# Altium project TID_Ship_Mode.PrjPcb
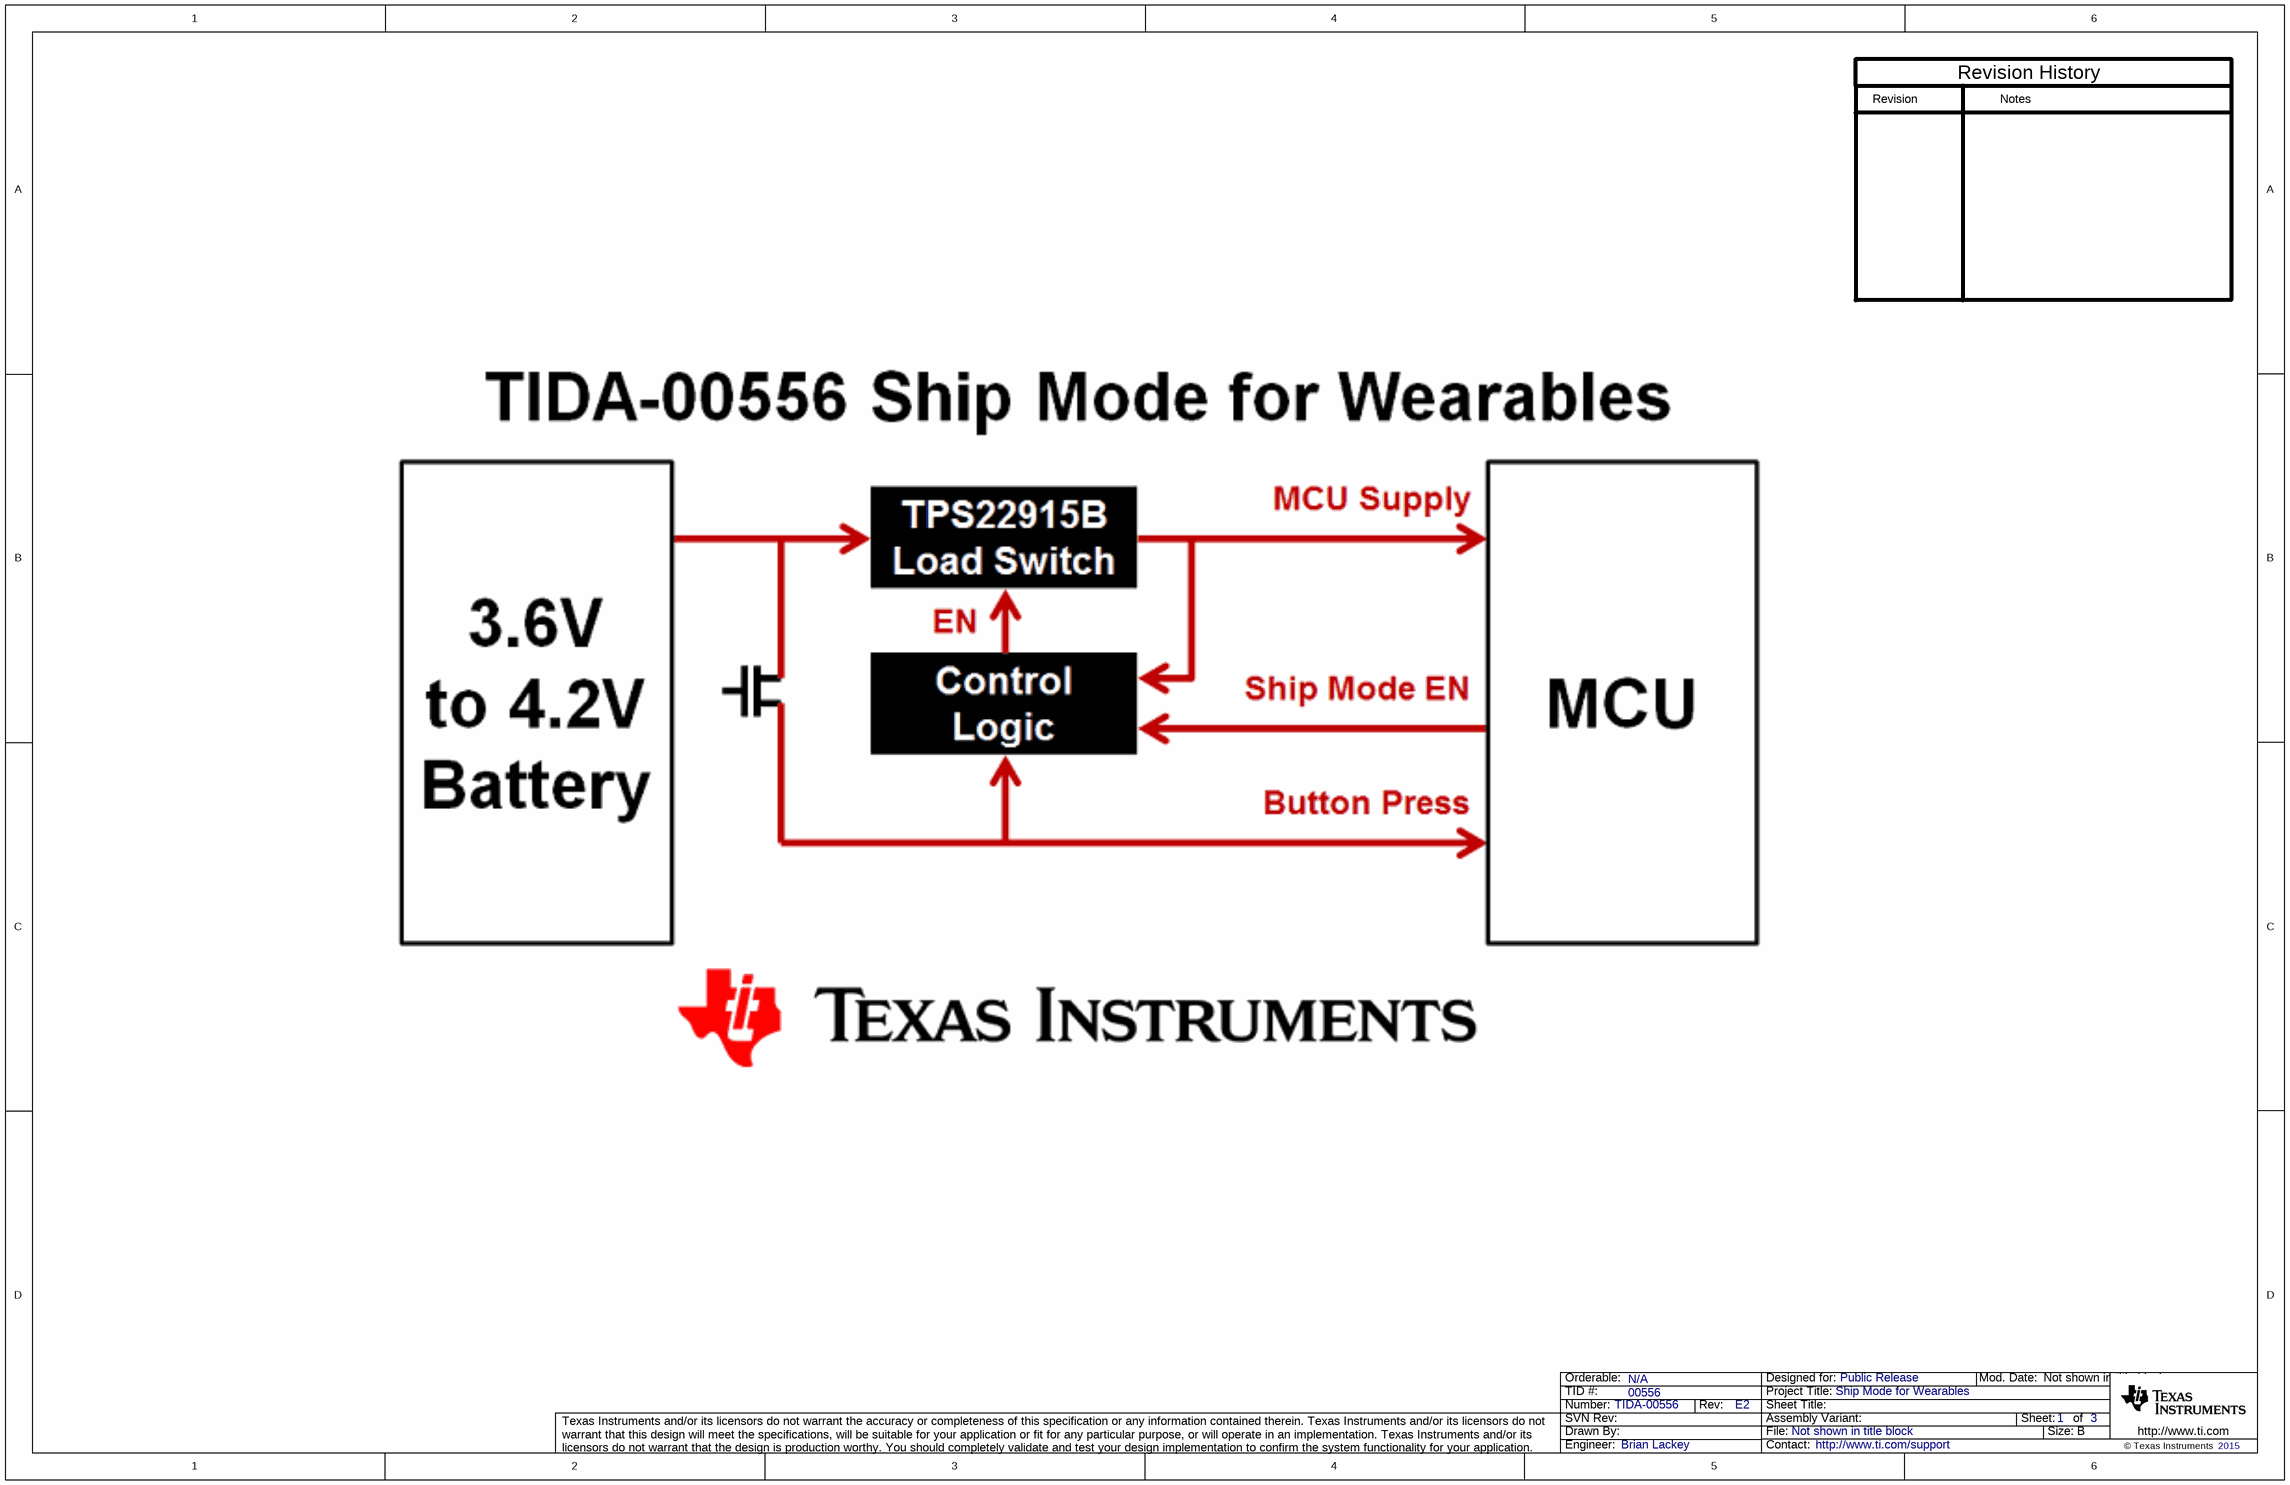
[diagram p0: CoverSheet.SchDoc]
CopyrightYear: 2015; EVM_Orderable: N/A; PCB_Rev: E2; PRJ_Customer: Public Release; PRJ_Engineer: Brian Lackey; PRJ_Number: TIDA-00556; PRJ_Title: Ship Mode for Wearables; SCH_Rev: E2; TechSupport: http://www.ti.com/support; TID: 00556
3 sheets, 41 parts. Net scope: global (net labels, ports and power ports of the same name join across sheets).
Board file: TID.PcbDoc
Sheets:
  CoverSheet.SchDoc
  TID_Hardware.SchDoc
  Ship_Mode_Circuit.SchDoc

## Sheet CoverSheet.SchDoc
size 431 x 279 mm; Date: Not shown in title block; ApprovedBy: Not shown in title block; CheckedBy: Not shown in title block; Author: Not shown in title block; CompanyName: Not shown in title block; Engineer: Not shown in title block; Organization: Not shown in title block; Address1: Not shown in title block; Address2: Not shown in title block; Address3: Not shown in title block; Address4: Not shown in title block; DocumentNumber: 1; Revision: Use project parameter SCH_Rev; SheetNumber: 1; SheetTotal: 3; PageSetup: Record=PageOptions¦CenterHorizontal=True¦CenterVertical=True¦PrintScale=1.00¦XCorrection=1.00¦YCorrection=1.00¦PrintKind=0¦BorderSize=5000000¦LeftOffset=0¦BottomOffset=0¦Orientation=2¦PaperLength=1000¦PaperWidth=1000¦Scale=100¦PaperSource=15¦PrintQuality=600¦MediaType=1¦DitherType=10¦PaperKind=Letter¦PrintScaleMode=1

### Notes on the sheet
- Revision
- Notes
- Revision History
- Place Block Diagram here (if appropriate) or delete this text box.
  If using a block diagram from another tool, save the picture as a .bmp file.
  Then, use menu Place|Drawing Tools|Graphic to insert the .png/.svg/.bmp file on the schematic.

## Sheet TID_Hardware.SchDoc
size 431 x 279 mm; Date: Not shown in title block; ApprovedBy: Not shown in title block; CheckedBy: Not shown in title block; Author: Not shown in title block; CompanyName: Not shown in title block; Engineer: Not shown in title block; Organization: Not shown in title block; Address1: Not shown in title block; Address2: Not shown in title block; Address3: Not shown in title block; Address4: Not shown in title block; DocumentNumber: 1; Revision: Use project parameter SCH_Rev; SheetNumber: 3; SheetTotal: 3; PageSetup: Record=PageOptions¦CenterHorizontal=True¦CenterVertical=True¦PrintScale=1.00¦XCorrection=1.00¦YCorrection=1.00¦PrintKind=0¦BorderSize=5000000¦LeftOffset=0¦BottomOffset=0¦Orientation=2¦PaperLength=1000¦PaperWidth=1000¦Scale=100¦PaperSource=15¦PrintQuality=600¦MediaType=1¦DitherType=10¦PaperKind=Letter¦PrintScaleMode=1
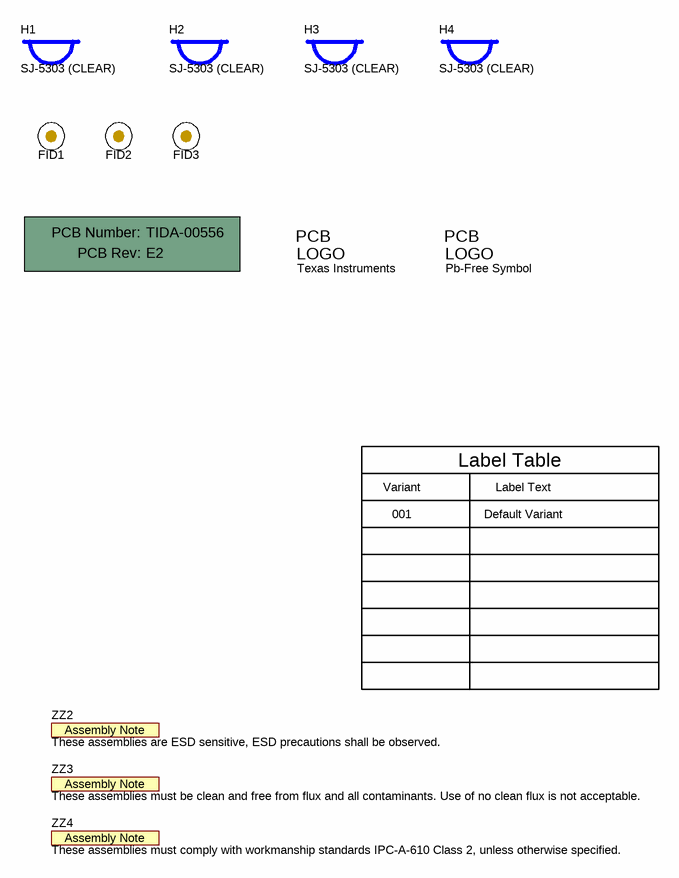
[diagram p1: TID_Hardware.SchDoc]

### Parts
!PCB  Printed Circuit Board  (value not drawn)  (mechanical)
FID1  Fiducial  [Fiducial10-20]  (value not drawn)
FID2  Fiducial  [Fiducial10-20]  (value not drawn)
FID3  Fiducial  [Fiducial10-20]  (value not drawn)
H1  SJ-5303 (CLEAR)  [Bumpon_SJ5003Transparent]
H2  SJ-5303 (CLEAR)  [Bumpon_SJ5003Transparent]
H3  SJ-5303 (CLEAR)  [Bumpon_SJ5003Transparent]
H4  SJ-5303 (CLEAR)  [Bumpon_SJ5003Transparent]
Logo1  Texas Instruments  [TI_Stacked_SolderMask_Small]  (no BOM)
Logo2  Pb-Free Symbol  [Pb-Free_Overlay_Small]  (no BOM)
ZZ2  These assemblies are ESD sensitive, ESD precautions shall be observed.  [AssemblyNote]  (no BOM)
ZZ3  These assemblies must be clean and free from flux and all contaminants. Use of no clean flux is not acceptable.  [AssemblyNote]  (no BOM)
ZZ4  These assemblies must comply with workmanship standards IPC-A-610 Class 2, unless otherwise specified.  [AssemblyNote]  (no BOM)

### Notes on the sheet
- Variant
- Label Table
- Label Text
- 001
- Default Variant

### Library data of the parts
!PCB = PCB: Manufacturer: Any; PartNumber: TIDA-00556; SymbolCreator: a0412235
FID1-FID3 = Fiducial: Fiducial mark.  There is nothing to buy or mount.; SymbolCreator: codlsc
H1-H4 = SJ-5303 (CLEAR): Bumpon, Hemisphere, 0.44 X 0.20, Clear; Manufacturer: 3M; SymbolCreator: a0412235
Logo1 = TI_Logo: Texas Instrument Corporate Signature; SymbolCreator: codlsc
Logo2 = Pb-Free: SymbolCreator: a0412235
ZZ2-ZZ4 = AssemblyNote: SymbolCreator: codlsc

## Sheet Ship_Mode_Circuit.SchDoc
size 431 x 279 mm; Date: Not shown in title block; ApprovedBy: Not shown in title block; CheckedBy: Not shown in title block; Author: Not shown in title block; CompanyName: Not shown in title block; Engineer: Not shown in title block; Organization: Not shown in title block; Address1: Not shown in title block; Address2: Not shown in title block; Address3: Not shown in title block; Address4: Not shown in title block; DocumentNumber: 1; Revision: Use project parameter SCH_Rev; SheetNumber: 2; SheetTotal: 3; PageSetup: Record=PageOptions¦CenterHorizontal=True¦CenterVertical=True¦PrintScale=1.00¦XCorrection=1.00¦YCorrection=1.00¦PrintKind=0¦BorderSize=5000000¦LeftOffset=0¦BottomOffset=0¦Orientation=2¦PaperLength=1000¦PaperWidth=1000¦Scale=100¦PaperSource=15¦PrintQuality=600¦MediaType=1¦DitherType=10¦PaperKind=Letter¦PrintScaleMode=1
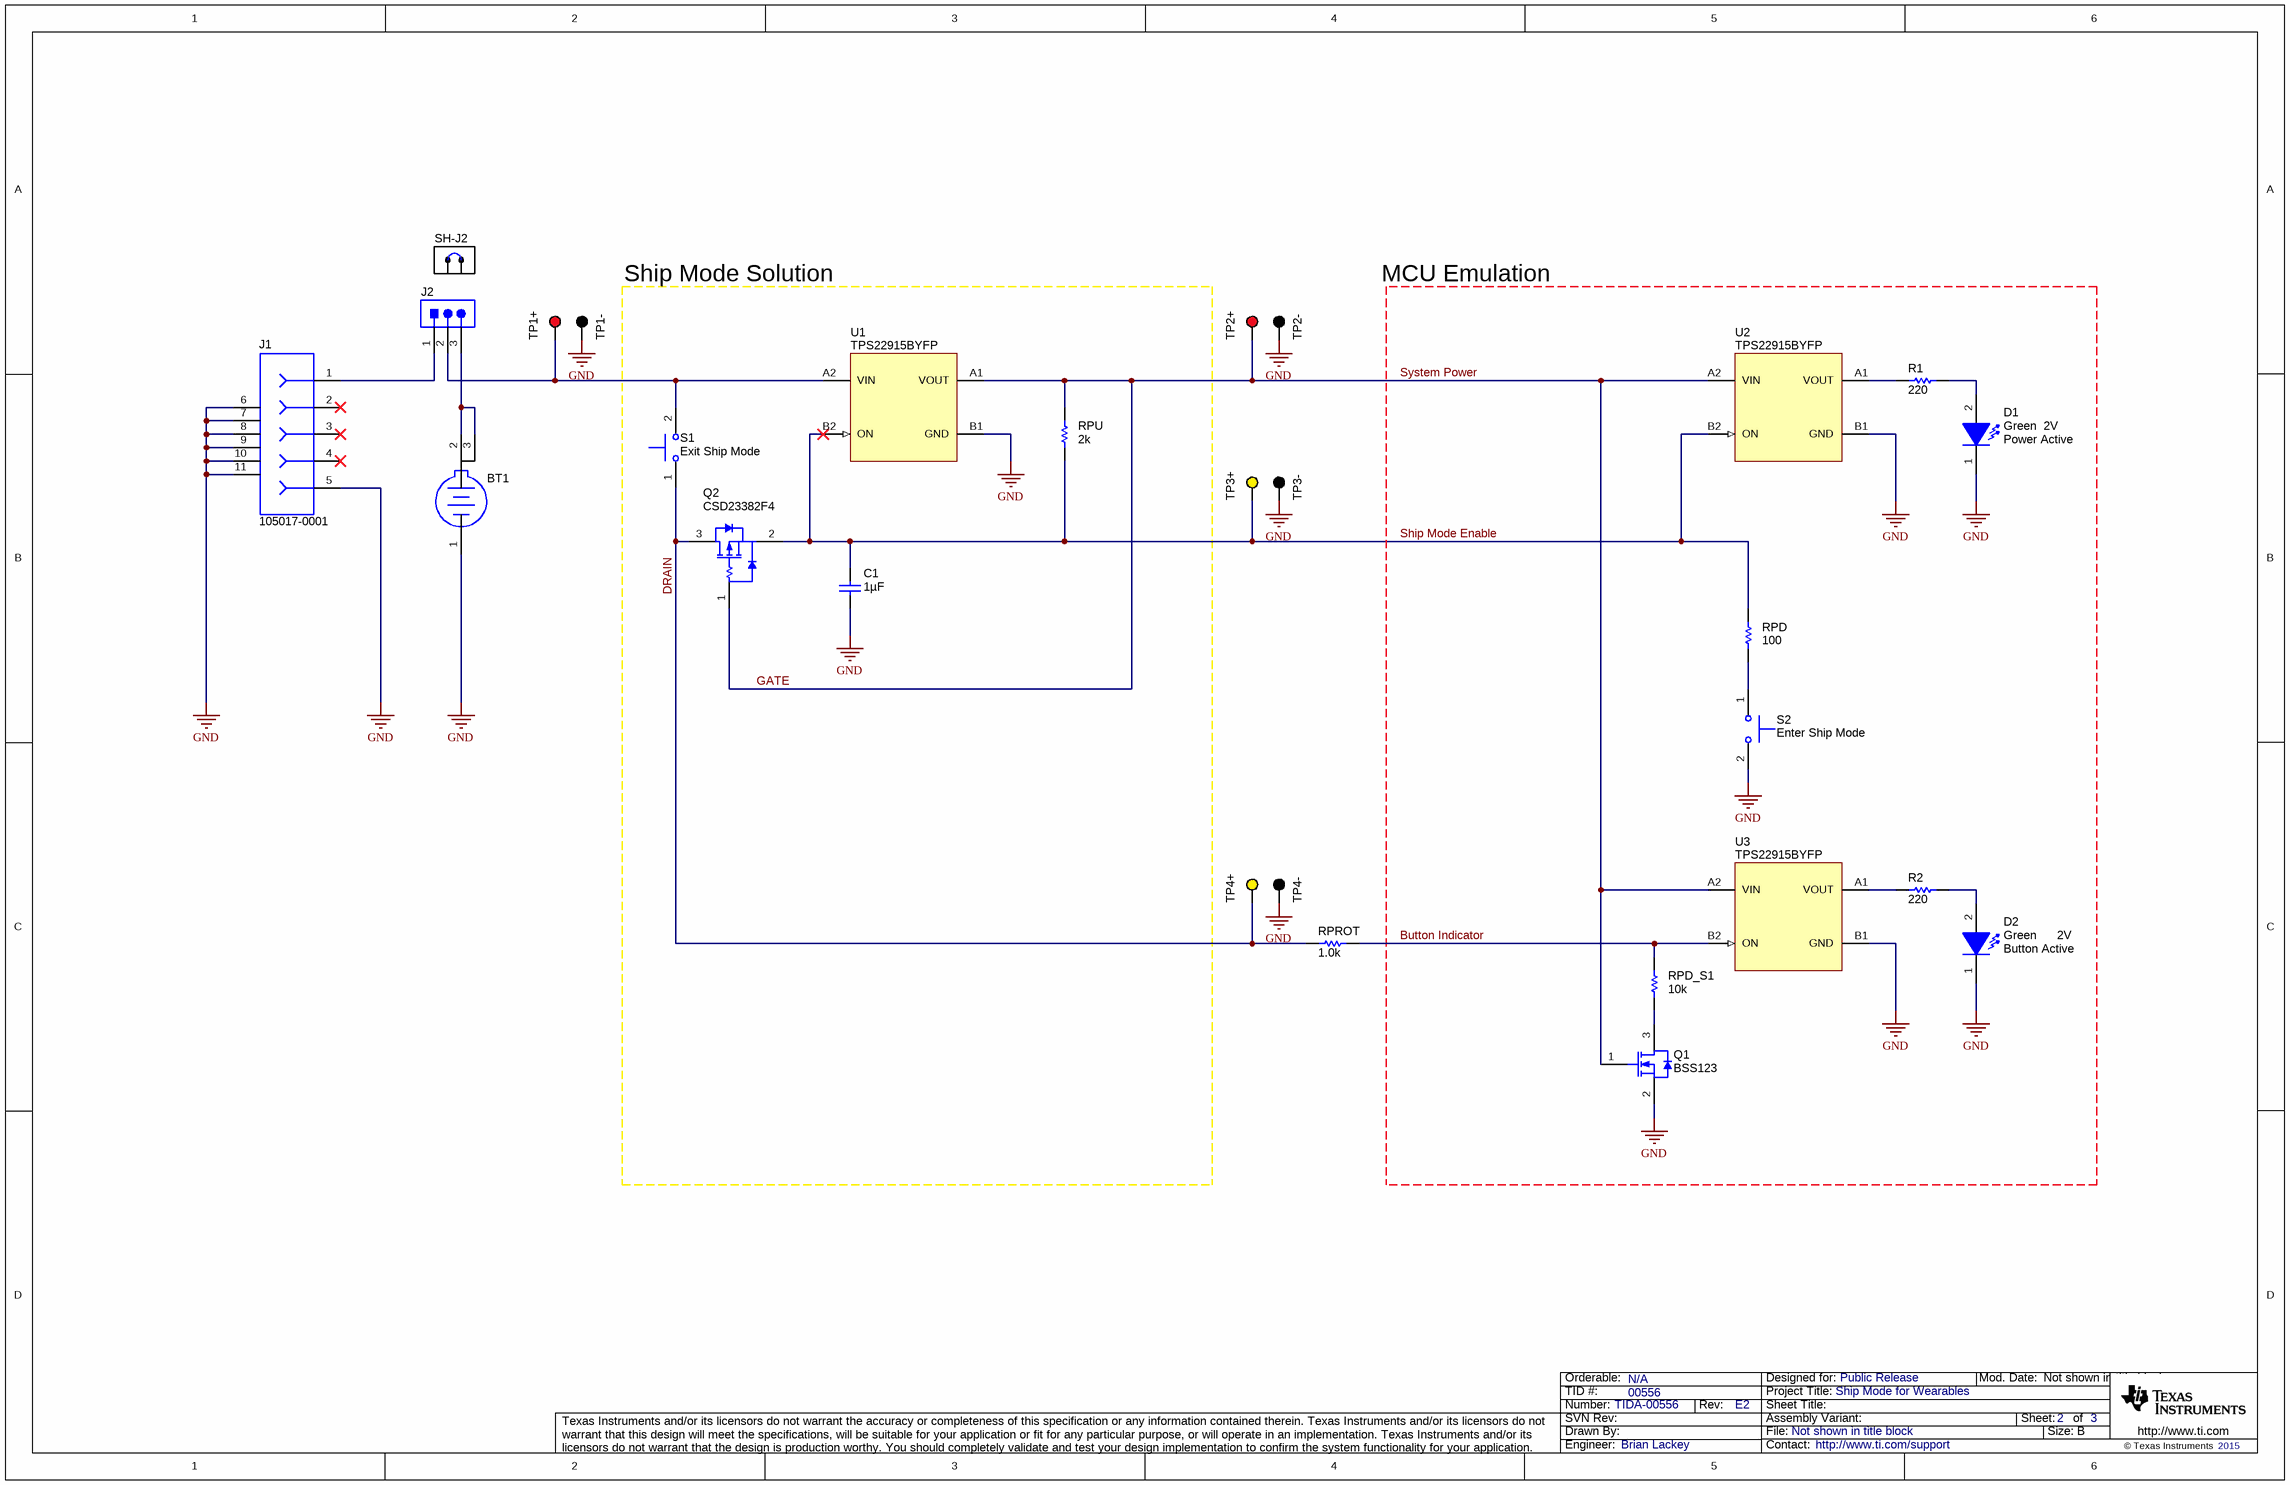
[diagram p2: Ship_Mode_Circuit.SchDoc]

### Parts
BT1  BAT-HLD-001  [LINX_BAT-HLD-001]  (value not drawn)
C1  ValueDisplayed: 1µF  [0201]  (hidden comment: CL03A105MP3NSNC)
D1  Power Active  value Green  Value2: 2V  [WL-SMCW_GREEN]
D2  Button Active  value Green  Value2: 2V  [WL-SMCW_GREEN]
J1  105017-0001  [CONN_105017-0001]
J2  61300311121  [WURTH_61300311121]  (value not drawn)
Q1  BSS123  [SOT-23]
Q2  CSD23382F4  [YJC0003A]
R1  ValueDisplayed: 220  [0603]  (hidden comment: CRCW0603220RJNEA)
R2  ValueDisplayed: 220  [0603]  (hidden comment: CRCW0603220RJNEA)
RPD  ValueDisplayed: 100  [0603]  (hidden comment: CRCW0603100RJNEA)
RPD_S1  ValueDisplayed: 10k  [0603]  (hidden comment: RC1608J103CS)
RPROT  ValueDisplayed: 1.0k  [0402]  (hidden comment: CRCW04021K00JNED)
RPU  ValueDisplayed: 2k  [0201M]  (hidden comment: RC0603F202CS)
S1  Exit Ship Mode  [SW_SKRKAEE010]
S2  Enter Ship Mode  [SW_SKRKAEE010]
SH-J2  969102-0000-DA  [SNT-100-BK-G]  (value not drawn)
TP1+  5000  [Keystone5000]  (value not drawn)
TP1-  5001  [Keystone5001]  (value not drawn)
TP2+  5000  [Keystone5000]  (value not drawn)
TP2-  5001  [Keystone5001]  (value not drawn)
TP3+  5004  [Keystone5004]  (value not drawn)
TP3-  5001  [Keystone5001]  (value not drawn)
TP4+  5004  [Keystone5004]  (value not drawn)
TP4-  5001  [Keystone5001]  (value not drawn)
U1  TPS22915BYFP  [YFP0004AAAA]
U2  TPS22915BYFP  [YFP0004AAAA]
U3  TPS22915BYFP  [YFP0004AAAA]

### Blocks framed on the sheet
Ship Mode Solution: C1 Q2 RPU S1 U1
MCU Emulation: D1 D2 Q1 R1 R2 RPD RPD_S1 S2 U2 U3

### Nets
GND: BT1.1(-) C1.2 D1.1(K) D2.1(K) J1.5 J1.6 J1.7 J1.8 J1.9 J1.10 J1.11 Q1.2(S) S2.2 TP1-.1 TP2-.1 TP3-.1 TP4-.1 U1.B1(GND) U2.B1(GND) U3.B1(GND)
Button Indicator: RPD_S1.2 RPROT.2 U3.B2(ON)
DRAIN: Q2.3(D) RPROT.1 S1.1 TP4+.1
GATE: Q1.1(G) Q2.1(G) RPU.2 TP2+.1 U1.A1(VOUT) U2.A2(VIN) U3.A2(VIN)  [also labelled System Power]
Ship Mode Enable: C1.1 Q2.2(S) RPD.2 RPU.1 TP3+.1 U1.B2(ON) U2.B2(ON)
NetBT1_2: BT1.2(+) BT1.3(+) J2.3
NetD1_2: D1.2(A) R1.2
NetD2_2: D2.2(A) R2.2
NetJ1_1: J1.1 J2.1
NetJ2_2: J2.2 S1.2 TP1+.1 U1.A2(VIN)
NetQ1_3: Q1.3(D) RPD_S1.1
NetR1_1: R1.1 U2.A1(VOUT)
NetR2_1: R2.1 U3.A1(VOUT)
NetRPD_1: RPD.1 S2.1

Not connected (* = marked no-connect by the designer): J1 2* 3* 4*

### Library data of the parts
BT1 = BAT-HLD-001: Battery Holder, Retainer clip, SMT; Manufacturer: Linx Technologies; SymbolCreator: a0411947
C1 = CL03A105MP3NSNC: CAP, CERM, 1 µF, 10 V, +/- 20%, X5R, 0201; Manufacturer: Samsung Electro-Mechanics; Polarized: N; CompType: Capacitor; Value: 1uF; U/M: EA; Cap_F: 0.000001; Tolerance_%: 20; Value1: Unknown; VDC_V: 10; Value2: 10V; TaMin_C: -55; TaMax_C: 85
D1 D2 = 150060VS75000: LED, Green, SMD; Manufacturer: Wurth Elektronik; Type: AlInGaP; Vf_V: 2; Io_A: 0.02; Value1: W; U/M: EA
J1 = 105017-0001: Connector, Receptacle, Micro-USB Type B, R/A, Bottom Mount SMT; Manufacturer: Molex; SymbolCreator: a0412235; U/M: EA
J2 = 61300311121: Header, 2.54 mm, 3x1, Gold, TH; Manufacturer: Wurth Elektronik; SymbolCreator: a0799628; U/M: EA
Q1 = BSS123: MOSFET, N-CH, 100 V, 0.17 A, SOT-23; Manufacturer: Fairchild Semiconductor; Alternate Manufacturer: None; U/M: EA; ChType: N; Value: 100V; VdsMax_V: 100; Value1: 10 ohm; Rdson45_ohm: 10; Value2: 1.8 nC; QgTyp_nC: 1.8; Vgs_V: 20; IdsMax_A: 0.17
Q2 = CSD23381F4: MOSFET, P-CH, -12 V, -3.5 A,; Manufacturer: Texas Instruments; Alternate Manufacturer: None; U/M: EA; ChType: P; Value: -12V; Value1: 0.066 ohm; Rdson45_ohm: 0.066; Value2: 1.04 nC; QgTyp_nC: 1.14; Vgs_V: 8
R1 R2 = CRCW0603220RJNEA: RES, 220, 5%, 0.1 W, 0603; Manufacturer: Vishay-Dale; CompType: Resistor; Value: 220; Value_Code: 220R; Tolerance_%: 5; Power_W: 0.1; Value2: 0.1W; VDC_V: 75; TempCo: 200 ppm/C; EIA_Code: E24; U/M: EA
RPD = CRCW0603100RJNEA: RES, 100, 5%, 0.1 W, 0603; Manufacturer: Vishay-Dale; CompType: Resistor; Value: 100; Value_Code: 100R; Tolerance_%: 5; Power_W: 0.1; Value2: 0.1W; VDC_V: 75; TempCo: 200 ppm/C; EIA_Code: E24; U/M: EA
RPD_S1 = RC1608J103CS: RES, 10 k, 5%, 0.1 W, 0603; Manufacturer: Samsung Electro-Mechanics; CompType: Resistor; Value: 10k; Res_ohm: 10000; Value_Code: 10k0; Tolerance_%: 5; Power_W: 0.1; Value2: 0.1W; VDC_V: 31; TempCo: 100 ppm/C; EIA_Code: E24; U/M: EA
RPROT = CRCW04021K00JNED: RES, 1.0 k, 5%, 0.063 W, 0402; Manufacturer: Vishay-Dale; CompType: Resistor; Value: 1.0k; Res_ohm: 1000; Value_Code: 1k00; Tolerance_%: 5; Power_W: 0.063; Value2: 0.063W; VDC_V: 50; TempCo: 200 ppm/C; EIA_Code: E24; U/M: EA
RPU = CRCW02011K80FKED: RES, 2 k, 1%, 0.05 W, 0201; Manufacturer: Samsung Electro-Mechanics America, Inc.; CompType: Resistor; Value: 2k; Res_ohm: 2000; Value_Code: 2k00; Tolerance_%: 1; Power_W: 0.05; Value2: 0.05W; VDC_V: 30; TempCo: 250 ppm/C; U/M: EA
S1 S2 = SKRKAEE010: Switch, Push Button, SMD; Manufacturer: Alps; SymbolCreator: a0412235; Circuit: SPST-NO; VDC_V: 12; SwitchFunction: Off-Mom; PositionCount: 1; CurrentRating_mA: 50
SH-J2 = 969102-0000-DA: Shunt, 100mil, Gold plated, Black; Manufacturer: 3M; Alternate Manufacturer: Samtec; Value: 1x2; Note: You can "mate" this to a header by matching the designator.  i.e. use SH-J3 for header J3
TP1+ TP2+ = 5000: Test Point, Miniature, Red, TH; Manufacturer: Keystone; CompType: Test Point Loop; U/M: EA
TP1- TP2- TP3- TP4- = 5001: Test Point, Miniature, Black, TH; Manufacturer: Keystone; CompType: Test Point Loop; U/M: EA
TP3+ TP4+ = 5004: Test Point, Miniature, Yellow, TH; Manufacturer: Keystone; CompType: Test Point Loop; U/M: EA
U1-U3 = TPS22915BYFP: Single Channel Ultra-Low Resistnace Load Switch, YFP0004AAAA; Manufacturer: Texas Instruments; SymbolCreator: a0799628; CompType: IC; U/M: EA

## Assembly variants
001: not fitted FID1 FID2 FID3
